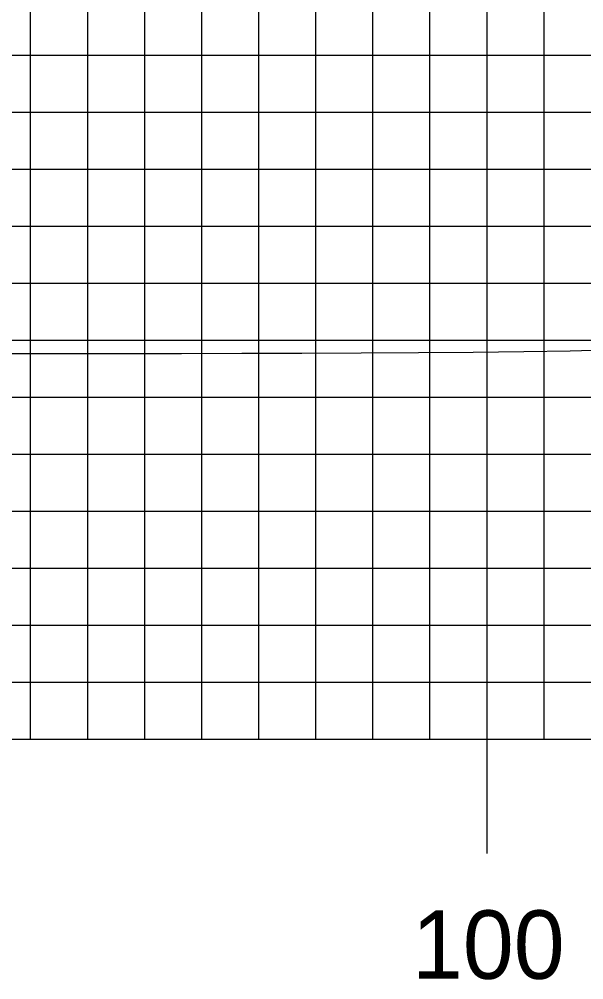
# Model space of a CAD drawing. Extents: x 1763365 to 1763708, y 442591 to 442811.
# Drawn here: x 1763422.6 to 1763432.5, y 442709.45 to 442726.29 of the extents above; entities that cross this region are included whole.
import ezdxf

# ---------------------------------------------------------------- set-up
doc = ezdxf.new("R2010")
doc.units = 0
for name, color, linetype in [('H_V ANNOTATION', 7, 'Continuous'), ('MAJOR', 7, 'Continuous'), ('MINOR', 7, 'Continuous'), ('S_Roadway_Centerline', 7, 'Continuous')]:
    doc.layers.add(name, color=color, linetype=linetype)

msp = doc.modelspace()

# ---------------------------------------------------------------- linework, layer by layer
at = {"layer": 'MAJOR'}
for p, q in [((1763430.805, 442713.665), (1763430.805, 442738.665)), ((1763390.805, 442723.665), (1763670.805, 442723.665)), ((1763390.805, 442718.665), (1763670.805, 442718.665)), ((1763390.805, 442713.665), (1763670.805, 442713.665)), ((1763390.805, 442713.665), (1763670.805, 442713.665)), ((1763430.805, 442711.661), (1763430.805, 442713.665))]:
    msp.add_line(p, q, dxfattribs=at)
at = {"layer": 'MINOR'}
for p, q in [((1763422.805, 442713.665), (1763422.805, 442738.665)), ((1763423.805, 442713.665), (1763423.805, 442738.665)), ((1763424.805, 442713.665), (1763424.805, 442738.665)), ((1763425.805, 442713.665), (1763425.805, 442738.665)), ((1763426.805, 442713.665), (1763426.805, 442738.665)), ((1763427.805, 442713.665), (1763427.805, 442738.665)), ((1763428.805, 442713.665), (1763428.805, 442738.665)), ((1763429.805, 442713.665), (1763429.805, 442738.665)), ((1763431.805, 442713.665), (1763431.805, 442738.665)), ((1763390.805, 442725.665), (1763670.805, 442725.665)), ((1763390.805, 442724.665), (1763670.805, 442724.665)), ((1763390.805, 442722.665), (1763670.805, 442722.665)), ((1763390.805, 442721.665), (1763670.805, 442721.665)), ((1763390.805, 442720.665), (1763670.805, 442720.665)), ((1763390.805, 442720.665), (1763670.805, 442720.665)), ((1763390.805, 442719.665), (1763670.805, 442719.665)), ((1763390.805, 442717.665), (1763670.805, 442717.665)), ((1763390.805, 442716.665), (1763670.805, 442716.665)), ((1763390.805, 442715.665), (1763670.805, 442715.665)), ((1763390.805, 442714.665), (1763670.805, 442714.665))]:
    msp.add_line(p, q, dxfattribs=at)
at = {"layer": 'S_Roadway_Centerline'}
msp.add_lwpolyline([(1763422.459, 442720.429), (1763423.406, 442720.429), (1763424.409, 442720.431), (1763425.447, 442720.432), (1763426.504, 442720.435), (1763427.56, 442720.438), (1763428.599, 442720.443), (1763429.604, 442720.449), (1763430.56, 442720.457), (1763431.452, 442720.467), (1763432.265, 442720.479), (1763432.867, 442720.493), (1763433.51, 442720.512), (1763434.178, 442720.537), (1763438.815, 442720.801), (1763440.002, 442720.854), (1763440.566, 442720.879), (1763441.098, 442720.902), (1763441.593, 442720.922), (1763442.047, 442720.938), (1763442.459, 442720.949)], dxfattribs=at)

# ---------------------------------------------------------------- texts
at = {"layer": 'H_V ANNOTATION'}
msp.add_text('100', height=1.2, dxfattribs=at).set_placement((1763429.489, 442709.465))

doc.saveas('drawing.dxf')
